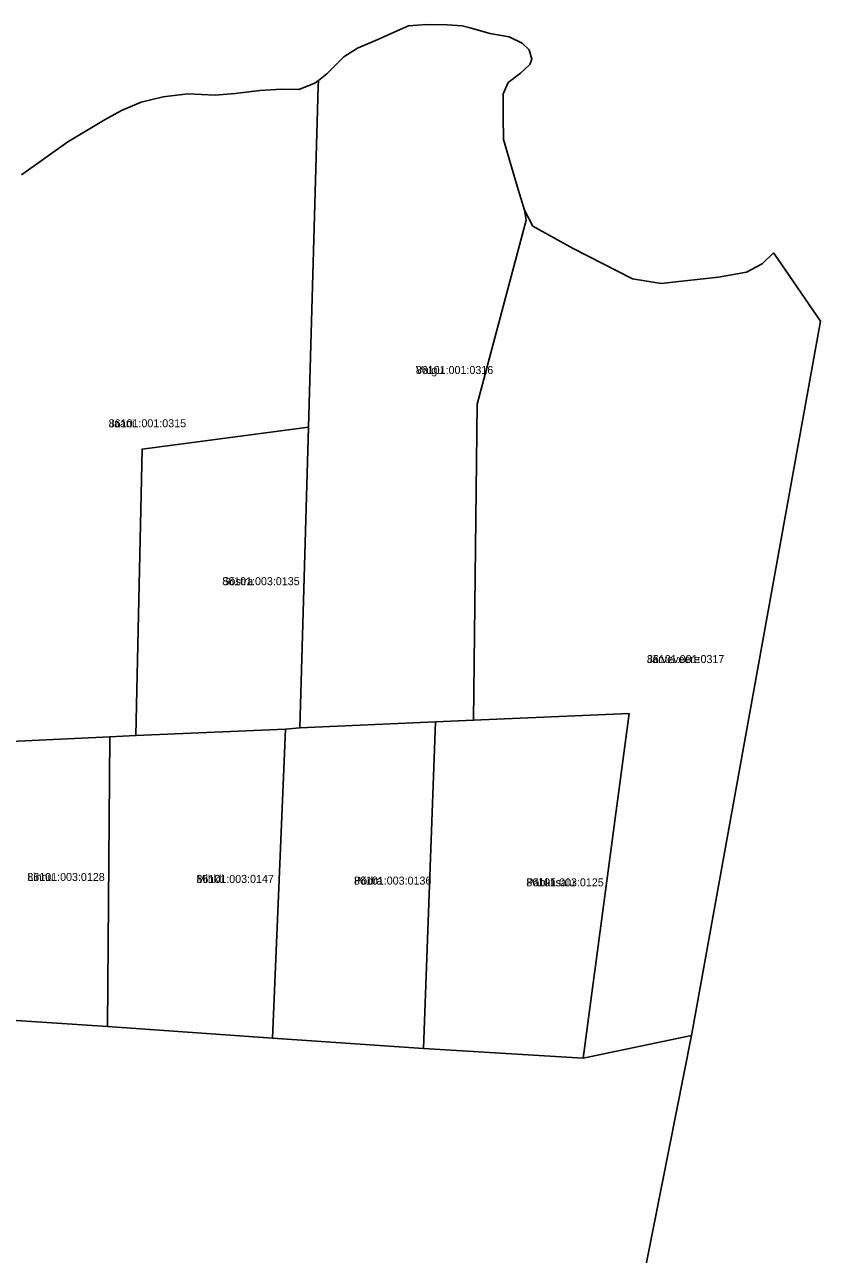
# Model space of a CAD drawing. Extents: x 663371 to 690098, y 6476568 to 6518353.
# Drawn here: x 671915.1 to 672064.2, y 6491244.3 to 6491474.7 of the extents above; entities that cross this region are included whole.
import ezdxf

# ---------------------------------------------------------------- set-up
doc = ezdxf.new("R2010")
doc.units = 0
for name, color, linetype in [('L_AADRESS', 7, 'Continuous'), ('PIIR', 7, 'Continuous'), ('TUNNUS', 7, 'Continuous')]:
    doc.layers.add(name, color=color, linetype=linetype)

msp = doc.modelspace()

# ---------------------------------------------------------------- linework, layer by layer
at = {"layer": 'PIIR'}
for points in [[(672020.53, 6491186.65), (672040.08, 6491285.29), (672064.21, 6491419.14), (672056.16, 6491430.87), (672055.4, 6491431.92), (672053.28, 6491429.89), (672050.38, 6491428.34), (672045.13, 6491427.4), (672038.25, 6491426.61), (672034.39, 6491426.17), (672028.98, 6491427.05), (672017.88, 6491432.74), (672010.32, 6491436.95), (672008.8, 6491439.93), (672007.42, 6491444.45), (672006.33, 6491448.07), (672004.84, 6491453.16), (672004.79, 6491457.54), (672004.8, 6491461.75), (672005.72, 6491463.85), (672007.99, 6491465.57), (672009.76, 6491467.22), (672010.12, 6491468.25), (672009.63, 6491469.97), (672008.35, 6491471.2), (672005.88, 6491472.39), (672002.3, 6491473.03), (671998.59, 6491474.08), (671997.06, 6491474.44), (671994.3, 6491474.68), (671990.42, 6491474.7), (671987.06, 6491474.47), (671983.76, 6491473.01), (671981.71, 6491472.1), (671977.45, 6491470.28), (671974.89, 6491468.65), (671971.74, 6491465.45), (671970.18, 6491464.24), (671969.47, 6491463.7), (671966.5, 6491462.54), (671963.21, 6491462.63), (671959.21, 6491462.38), (671954.55, 6491461.81), (671950.82, 6491461.45), (671945.66, 6491461.72), (671941.04, 6491461.16), (671936.93, 6491460.14), (671933.27, 6491458.63), (671930.22, 6491456.93), (671923.2, 6491452.74), (671914.5, 6491446.52)], [(671914.5, 6491446.52), (671923.2, 6491452.74), (671930.22, 6491456.93), (671933.27, 6491458.63), (671936.93, 6491460.14), (671941.04, 6491461.16), (671945.66, 6491461.72), (671950.82, 6491461.45), (671954.55, 6491461.81), (671959.21, 6491462.38), (671963.21, 6491462.63), (671966.5, 6491462.54), (671969.47, 6491463.7), (671970.18, 6491464.24), (671970.08, 6491463.12), (671968.31, 6491399.26), (671937.12, 6491395.17), (671935.97, 6491341.48), (671931.05, 6491341.23), (671904.54, 6491340.01)]]:
    msp.add_lwpolyline(points, dxfattribs=at)
for points in [[(671992.1, 6491344.06), (671966.7, 6491342.93), (671968.31, 6491399.26), (671970.08, 6491463.12), (671970.18, 6491464.24), (671971.74, 6491465.45), (671974.89, 6491468.65), (671977.45, 6491470.28), (671981.71, 6491472.1), (671983.76, 6491473.01), (671987.06, 6491474.47), (671990.42, 6491474.7), (671994.3, 6491474.68), (671997.06, 6491474.44), (671998.59, 6491474.08), (672002.3, 6491473.03), (672005.88, 6491472.39), (672008.35, 6491471.2), (672009.63, 6491469.97), (672010.12, 6491468.25), (672009.76, 6491467.22), (672007.99, 6491465.57), (672005.72, 6491463.85), (672004.8, 6491461.75), (672004.79, 6491457.54), (672004.84, 6491453.16), (672006.33, 6491448.07), (672007.42, 6491444.45), (672008.8, 6491439.93), (672009.1, 6491438.05), (671999.9, 6491403.58), (671999.22, 6491344.36)], [(672009.1, 6491438.05), (672008.8, 6491439.93), (672010.32, 6491436.95), (672017.88, 6491432.74), (672028.98, 6491427.05), (672034.39, 6491426.17), (672038.25, 6491426.61), (672045.13, 6491427.4), (672050.38, 6491428.34), (672053.28, 6491429.89), (672055.4, 6491431.92), (672056.16, 6491430.87), (672064.21, 6491419.14), (672040.08, 6491285.29), (672019.74, 6491281.04), (672028.36, 6491345.6), (671999.22, 6491344.36), (671999.9, 6491403.58)], [(671968.31, 6491399.26), (671966.7, 6491342.93), (671963.98, 6491342.68), (671935.97, 6491341.48), (671937.12, 6491395.17)], [(671999.22, 6491344.36), (672028.36, 6491345.6), (672019.74, 6491281.04), (671989.85, 6491282.84), (671992.1, 6491344.06)], [(671966.7, 6491342.93), (671992.1, 6491344.06), (671989.85, 6491282.84), (671961.54, 6491284.8), (671963.98, 6491342.68)], [(671904.54, 6491340.01), (671931.05, 6491341.23), (671930.64, 6491286.97), (671900.2, 6491288.98), (671900.52, 6491339.8)], [(671935.97, 6491341.48), (671963.98, 6491342.68), (671961.54, 6491284.8), (671930.64, 6491286.97), (671931.05, 6491341.23)], [(671735.36, 6491298.92), (671735.49, 6491300.05), (671741.11, 6491299.76), (671775.55, 6491297.33), (671807.16, 6491295.29), (671839.54, 6491293.1), (671869.97, 6491291.04), (671900.2, 6491288.98), (671930.64, 6491286.97), (671961.54, 6491284.8), (671989.85, 6491282.84), (672019.74, 6491281.04), (672040.08, 6491285.29), (672020.53, 6491186.65), (671735.06, 6491152.04)]]:
    msp.add_lwpolyline(points, close=True, dxfattribs=at)

# ---------------------------------------------------------------- texts
at = {"layer": 'L_AADRESS'}
for s, p in [('Valgu', (671988.41, 6491409.23)), ('Jaani', (671930.86, 6491399.25)), ('Sõstra', (671952.14, 6491369.66)), ('Järveveere', (672031.71, 6491355.07)), ('Linnu', (671915.62, 6491314.24)), ('Mihkli', (671947.31, 6491313.88)), ('Põdra', (671976.82, 6491313.56)), ('Pähklisalu', (672009.11, 6491313.23))]:
    msp.add_text(s, height=1.5, dxfattribs=at).set_placement(p)
at = {"layer": 'TUNNUS'}
for s, p in [('86101:001:0316', (671988.41, 6491409.23)), ('86101:001:0315', (671930.86, 6491399.25)), ('86101:003:0135', (671952.14, 6491369.66)), ('86101:001:0317', (672031.71, 6491355.07)), ('86101:003:0128', (671915.62, 6491314.24)), ('86101:003:0147', (671947.31, 6491313.88)), ('86101:003:0136', (671976.82, 6491313.56)), ('86101:003:0125', (672009.11, 6491313.23))]:
    msp.add_text(s, height=1.5, dxfattribs=at).set_placement(p)

doc.saveas('drawing.dxf')
